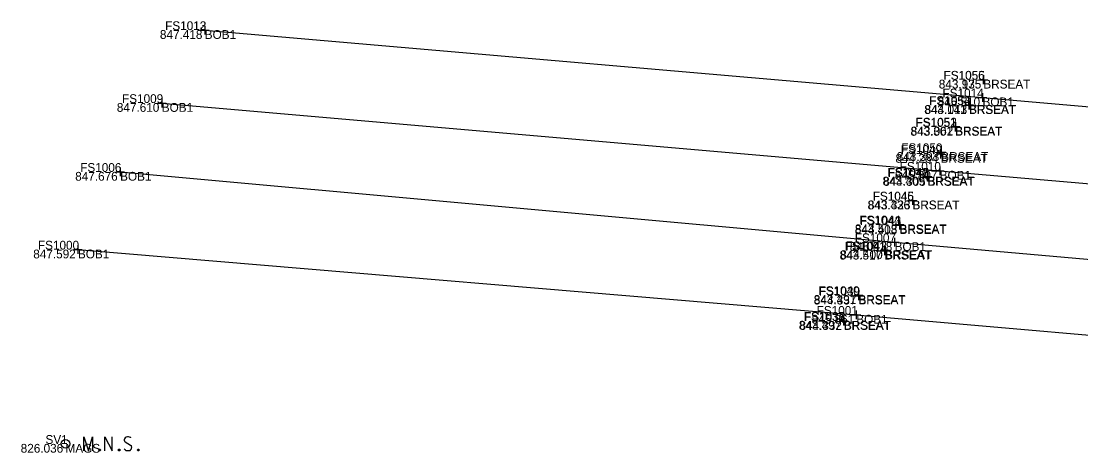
# Model space of a CAD drawing. Extents: x 1455931 to 1456172, y 560190 to 560355.
# Drawn here: x 1455931 to 1456051.6, y 560190.4 to 560239.5 of the extents above; entities that cross this region are included whole.
import ezdxf

# ---------------------------------------------------------------- set-up
doc = ezdxf.new("R2010")
doc.units = 0
for name, color, linetype in [('BR_X_SV_Beam_Seat', 7, 'Continuous'), ('BR_X_SV_Bottom_of_Beam', 7, 'Continuous'), ('BR_X_SV_Bottom_of_Beam_Text', 7, 'Continuous'), ('BR_X_SV_Shot_Marker', 7, 'Continuous'), ('SV_P_Control_Cells_Set', 7, 'Continuous'), ('SV_X_Shot_Marker', 7, 'Continuous'), ('SV_X_Text_Comment', 7, 'Continuous'), ('SV_X_Text_Elevation', 7, 'Continuous'), ('SV_X_Text_Name', 7, 'Continuous')]:
    doc.layers.add(name, color=color, linetype=linetype)

msp = doc.modelspace()

# ---------------------------------------------------------------- linework, layer by layer
at = {"layer": 'BR_X_SV_Bottom_of_Beam'}
for points in [[(1455951.93, 560238.47), (1455951.93, 560238.47), (1456040.42, 560230.81), (1456129.8, 560223.03)], [(1455947.04, 560230.18), (1456035.55, 560222.47), (1456125.23, 560214.75)], [(1455942.3, 560222.35), (1456030.42, 560214.36), (1456120.23, 560206.46)], [(1455937.5, 560213.52), (1456026.06, 560206.1), (1456114.85, 560198.36), (1456168.66, 560193.7)]]:
    msp.add_lwpolyline(points, dxfattribs=at)
at = {"layer": 'BR_X_SV_Shot_Marker'}
for p, q in [((1456040.51, 560233.33), (1456040.51, 560232.33)), ((1456040.52, 560233.33), (1456040.52, 560232.33)), ((1456040.01, 560232.83), (1456041.01, 560232.83)), ((1456040.02, 560232.83), (1456041.02, 560232.83)), ((1456040.51, 560232.83), (1456040.51, 560232.83)), ((1456040.52, 560232.83), (1456040.52, 560232.83)), ((1456038.37, 560229.93), (1456039.37, 560229.93)), ((1456038.4, 560229.96), (1456039.4, 560229.96)), ((1456038.87, 560230.43), (1456038.87, 560229.43)), ((1456038.87, 560229.93), (1456038.87, 560229.93)), ((1456038.9, 560230.46), (1456038.9, 560229.46)), ((1456038.9, 560229.96), (1456038.9, 560229.96)), ((1456036.8, 560227.46), (1456037.8, 560227.46)), ((1456036.83, 560227.5), (1456037.83, 560227.5)), ((1456037.3, 560227.96), (1456037.3, 560226.96)), ((1456037.3, 560227.46), (1456037.3, 560227.46)), ((1456037.33, 560228), (1456037.33, 560227)), ((1456037.33, 560227.5), (1456037.33, 560227.5)), ((1456035.65, 560224.89), (1456035.65, 560223.89)), ((1456035.73, 560225.1), (1456035.73, 560224.1)), ((1456035.15, 560224.39), (1456036.15, 560224.39)), ((1456035.23, 560224.6), (1456036.23, 560224.6)), ((1456035.65, 560224.39), (1456035.65, 560224.39)), ((1456035.73, 560224.6), (1456035.73, 560224.6)), ((1456034.14, 560222.31), (1456034.14, 560221.31)), ((1456034.19, 560222.27), (1456034.19, 560221.27)), ((1456033.64, 560221.81), (1456034.64, 560221.81)), ((1456033.69, 560221.77), (1456034.69, 560221.77)), ((1456034.14, 560221.81), (1456034.14, 560221.81)), ((1456034.19, 560221.77), (1456034.19, 560221.77)), ((1456031.94, 560219.09), (1456032.94, 560219.09)), ((1456031.96, 560219.1), (1456032.96, 560219.1)), ((1456032.44, 560219.59), (1456032.44, 560218.59)), ((1456032.44, 560219.09), (1456032.44, 560219.09)), ((1456032.46, 560219.6), (1456032.46, 560218.6)), ((1456032.46, 560219.1), (1456032.46, 560219.1)), ((1456030.47, 560216.38), (1456031.47, 560216.38)), ((1456030.49, 560216.3), (1456031.49, 560216.3)), ((1456030.97, 560216.88), (1456030.97, 560215.88)), ((1456030.97, 560216.38), (1456030.97, 560216.38)), ((1456030.99, 560216.8), (1456030.99, 560215.8)), ((1456030.99, 560216.3), (1456030.99, 560216.3)), ((1456029.26, 560213.89), (1456029.26, 560212.89)), ((1456029.35, 560213.94), (1456029.35, 560212.94)), ((1456028.76, 560213.39), (1456029.76, 560213.39)), ((1456028.85, 560213.44), (1456029.85, 560213.44)), ((1456029.26, 560213.39), (1456029.26, 560213.39)), ((1456029.35, 560213.44), (1456029.35, 560213.44)), ((1456025.8, 560208.35), (1456026.8, 560208.35)), ((1456025.82, 560208.28), (1456026.82, 560208.28)), ((1456026.3, 560208.85), (1456026.3, 560207.85)), ((1456026.3, 560208.35), (1456026.3, 560208.35)), ((1456026.32, 560208.78), (1456026.32, 560207.78)), ((1456026.32, 560208.28), (1456026.32, 560208.28)), ((1456024.11, 560205.42), (1456025.11, 560205.42)), ((1456024.16, 560205.39), (1456025.16, 560205.39)), ((1456024.61, 560205.92), (1456024.61, 560204.92)), ((1456024.61, 560205.42), (1456024.61, 560205.42)), ((1456024.66, 560205.89), (1456024.66, 560204.89)), ((1456024.66, 560205.39), (1456024.66, 560205.39))]:
    msp.add_line(p, q, dxfattribs=at)
at = {"layer": 'SV_P_Control_Cells_Set'}
for points in [[(1455938.18, 560190.63), (1455938.18, 560192.23), (1455938.69, 560190.63), (1455939.17, 560192.23), (1455939.17, 560190.63)], [(1455940.55, 560190.63), (1455940.55, 560192.23), (1455941.38, 560190.63), (1455941.38, 560192.23)], [(1455943.53, 560192.12), (1455943.51, 560192.15), (1455943.47, 560192.17), (1455943.37, 560192.21), (1455943.25, 560192.23), (1455943.16, 560192.23), (1455943.13, 560192.23), (1455942.99, 560192.2), (1455942.87, 560192.12), (1455942.79, 560192.02), (1455942.77, 560191.92), (1455942.77, 560191.84), (1455942.79, 560191.74), (1455942.88, 560191.65), (1455943.48, 560191.28), (1455943.54, 560191.23), (1455943.56, 560191.18), (1455943.58, 560191.1), (1455943.58, 560191.02), (1455943.57, 560190.95), (1455943.56, 560190.9), (1455943.54, 560190.83), (1455943.52, 560190.78), (1455943.5, 560190.75), (1455943.46, 560190.71), (1455943.43, 560190.68), (1455943.39, 560190.66), (1455943.35, 560190.65), (1455943.25, 560190.63), (1455943.1, 560190.63), (1455943, 560190.66), (1455942.86, 560190.75), (1455942.77, 560190.82)], [(1455939.95, 560190.85), (1455940, 560190.85), (1455940.03, 560190.82), (1455940.07, 560190.77), (1455940.07, 560190.71), (1455940.03, 560190.66), (1455940, 560190.63), (1455939.95, 560190.63), (1455939.91, 560190.66), (1455939.88, 560190.71), (1455939.88, 560190.77), (1455939.91, 560190.82), (1455939.95, 560190.85)], [(1455942.16, 560190.85), (1455942.22, 560190.85), (1455942.25, 560190.82), (1455942.28, 560190.77), (1455942.28, 560190.71), (1455942.25, 560190.66), (1455942.22, 560190.63), (1455942.16, 560190.63), (1455942.13, 560190.66), (1455942.1, 560190.71), (1455942.1, 560190.77), (1455942.13, 560190.82), (1455942.16, 560190.85)], [(1455944.34, 560190.85), (1455944.4, 560190.85), (1455944.43, 560190.82), (1455944.47, 560190.77), (1455944.47, 560190.71), (1455944.43, 560190.66), (1455944.4, 560190.63), (1455944.34, 560190.63), (1455944.31, 560190.66), (1455944.28, 560190.71), (1455944.28, 560190.77), (1455944.31, 560190.82), (1455944.34, 560190.85)]]:
    msp.add_lwpolyline(points, dxfattribs=at)
msp.add_circle((1455936.09, 560191.43), 0.497, dxfattribs=at)
at = {"layer": 'SV_X_Shot_Marker'}
for p, q in [((1455951.43, 560238.47), (1455952.43, 560238.47)), ((1455951.43, 560238.47), (1455952.43, 560238.47)), ((1455951.93, 560238.97), (1455951.93, 560237.97)), ((1455951.93, 560238.97), (1455951.93, 560237.97)), ((1455951.93, 560238.47), (1455951.93, 560238.47)), ((1455951.93, 560238.47), (1455951.93, 560238.47)), ((1456039.92, 560230.81), (1456040.92, 560230.81)), ((1456040.42, 560231.31), (1456040.42, 560230.31)), ((1456040.42, 560230.81), (1456040.42, 560230.81)), ((1455946.54, 560230.18), (1455947.54, 560230.18)), ((1455947.04, 560230.68), (1455947.04, 560229.68)), ((1455947.04, 560230.18), (1455947.04, 560230.18)), ((1455941.8, 560222.35), (1455942.8, 560222.35)), ((1455942.3, 560222.85), (1455942.3, 560221.85)), ((1455942.3, 560222.35), (1455942.3, 560222.35)), ((1456035.05, 560222.47), (1456036.05, 560222.47)), ((1456035.55, 560222.97), (1456035.55, 560221.97)), ((1456035.55, 560222.47), (1456035.55, 560222.47)), ((1455937.5, 560214.02), (1455937.5, 560213.02)), ((1456029.92, 560214.36), (1456030.92, 560214.36)), ((1456030.42, 560214.86), (1456030.42, 560213.86)), ((1456030.42, 560214.36), (1456030.42, 560214.36)), ((1455937, 560213.52), (1455938, 560213.52)), ((1455937.5, 560213.52), (1455937.5, 560213.52)), ((1456026.06, 560206.6), (1456026.06, 560205.6)), ((1456025.56, 560206.1), (1456026.56, 560206.1)), ((1456026.06, 560206.1), (1456026.06, 560206.1))]:
    msp.add_line(p, q, dxfattribs=at)

# ---------------------------------------------------------------- texts
at = {"layer": 'BR_X_SV_Beam_Seat'}
for s, p in [('FS1056', (1456035.98, 560232.83)), ('FS1055', (1456036, 560232.83)), ('843.975', (1456035.44, 560231.83)), ('843.135', (1456035.45, 560231.83)), ('BRSEAT', (1456040.51, 560231.83)), ('BRSEAT', (1456040.52, 560231.83)), ('FS1054', (1456034.35, 560229.96)), ('FS1053', (1456034.38, 560229.93)), ('843.141', (1456033.79, 560228.93)), ('844.013', (1456033.84, 560228.96)), ('BRSEAT', (1456038.87, 560228.93)), ('BRSEAT', (1456038.9, 560228.96)), ('FS1051', (1456032.79, 560227.46)), ('FS1052', (1456032.82, 560227.5)), ('843.301', (1456032.22, 560226.46)), ('843.062', (1456032.26, 560226.5)), ('BRSEAT', (1456037.3, 560226.46)), ('BRSEAT', (1456037.33, 560226.5)), ('FS1049', (1456031.13, 560224.39)), ('FS1050', (1456031.18, 560224.6)), ('844.284', (1456030.52, 560223.39)), ('843.393', (1456030.66, 560223.6)), ('BRSEAT', (1456035.65, 560223.39)), ('BRSEAT', (1456035.73, 560223.6)), ('FS1047', (1456029.61, 560221.81)), ('FS1048', (1456029.66, 560221.77)), ('843.409', (1456029.05, 560220.81)), ('844.305', (1456029.12, 560220.77)), ('BRSEAT', (1456034.14, 560220.81)), ('BRSEAT', (1456034.19, 560220.77)), ('FS1046', (1456027.92, 560219.1)), ('FS1045', (1456027.94, 560219.09)), ('843.436', (1456027.34, 560218.09)), ('843.323', (1456027.39, 560218.1)), ('BRSEAT', (1456032.44, 560218.09)), ('BRSEAT', (1456032.46, 560218.1)), ('844.408', (1456025.89, 560215.3)), ('843.513', (1456025.9, 560215.38)), ('FS1044', (1456026.41, 560216.38)), ('FS1043', (1456026.49, 560216.3)), ('BRSEAT', (1456030.97, 560215.38)), ('BRSEAT', (1456030.99, 560215.3)), ('FS1041', (1456024.74, 560213.39)), ('FS1042', (1456024.84, 560213.44)), ('843.517', (1456024.16, 560212.39)), ('844.400', (1456024.23, 560212.44)), ('BRSEAT', (1456029.26, 560212.39)), ('BRSEAT', (1456029.35, 560212.44)), ('FS1040', (1456021.76, 560208.35)), ('FS1039', (1456021.81, 560208.28)), ('843.491', (1456021.22, 560207.35)), ('844.337', (1456021.23, 560207.28)), ('BRSEAT', (1456026.3, 560207.35)), ('BRSEAT', (1456026.32, 560207.28)), ('843.497', (1456019.52, 560204.42)), ('844.332', (1456019.59, 560204.39)), ('FS1037', (1456020.08, 560205.42)), ('FS1038', (1456020.13, 560205.39)), ('BRSEAT', (1456024.61, 560204.42)), ('BRSEAT', (1456024.66, 560204.39))]:
    msp.add_text(s, height=1, dxfattribs=at).set_placement(p)
at = {"layer": 'BR_X_SV_Bottom_of_Beam_Text'}
for s, p in [('FS1012', (1455947.42, 560238.47)), ('FS1013', (1455947.43, 560238.47)), ('847.418', (1455946.83, 560237.47)), ('847.418', (1455946.83, 560237.47)), ('BOB1', (1455951.93, 560237.47)), ('BOB1', (1455951.93, 560237.47)), ('FS1009', (1455942.52, 560230.18)), ('845.510', (1456035.31, 560229.81)), ('FS1014', (1456035.87, 560230.81)), ('BOB1', (1456040.42, 560229.81)), ('847.610', (1455941.93, 560229.18)), ('BOB1', (1455947.04, 560229.18)), ('FS1010', (1456031, 560222.47)), ('847.676', (1455937.19, 560221.35)), ('FS1006', (1455937.76, 560222.35)), ('BOB1', (1455942.3, 560221.35)), ('845.807', (1456030.45, 560221.47)), ('BOB1', (1456035.55, 560221.47)), ('FS1007', (1456025.89, 560214.36)), ('FS1000', (1455932.95, 560213.52)), ('845.918', (1456025.32, 560213.36)), ('BOB1', (1456030.42, 560213.36)), ('847.592', (1455932.42, 560212.52)), ('BOB1', (1455937.5, 560212.52)), ('FS1001', (1456021.55, 560206.1)), ('845.861', (1456020.98, 560205.1)), ('BOB1', (1456026.06, 560205.1))]:
    msp.add_text(s, height=1, dxfattribs=at).set_placement(p)
at = {"layer": 'SV_X_Text_Comment'}
msp.add_text('MAGS', height=1, dxfattribs=at).set_placement((1455936.09, 560190.43))
at = {"layer": 'SV_X_Text_Elevation'}
msp.add_text('826.036', height=1, dxfattribs=at).set_placement((1455930.99, 560190.43))
at = {"layer": 'SV_X_Text_Name'}
msp.add_text('SV1', height=1, dxfattribs=at).set_placement((1455933.81, 560191.43))

doc.saveas('drawing.dxf')
